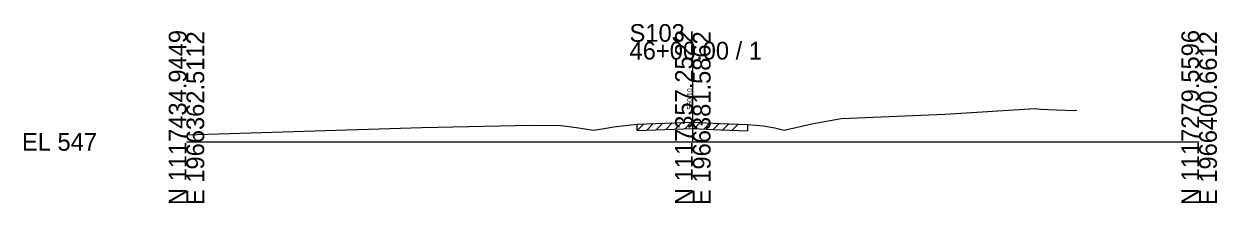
# Model space of a CAD drawing. Extents: x -26 to 163, y -10 to 45020.
# Drawn here: x -25.7 to 162.8, y 5990.3 to 6018.7 of the extents above; entities that cross this region are included whole.
import ezdxf

# ---------------------------------------------------------------- set-up
doc = ezdxf.new("R2010")
doc.units = 0
for name, color, linetype in [('RD_GPK_XS_Cell', 7, 'Continuous'), ('RD_XS_ExGround', 7, 'Continuous'), ('RD_XS_ExPaveRet', 7, 'Continuous'), ('RD_XS_TX_Elev_EX', 7, 'Continuous')]:
    doc.layers.add(name, color=color, linetype=linetype)

msp = doc.modelspace()

# ---------------------------------------------------------------- linework, layer by layer
at = {"layer": 'RD_GPK_XS_Cell'}
for p, q in [((80, 6000), (80, 6015.82)), ((0, 6000), (80, 6000)), ((80, 6000), (160, 6000))]:
    msp.add_line(p, q, dxfattribs=at)
at = {"layer": 'RD_XS_ExGround'}
for p, q in [((119.84, 6004.36), (134.09, 6005.27)), ((134.09, 6005.27), (134.94, 6005.19)), ((134.94, 6005.19), (140.08, 6004.96)), ((140.08, 6004.96), (140.68, 6005.02)), ((71.22, 6002.8), (75.57, 6002.96)), ((75.57, 6002.96), (79.95, 6003.11)), ((79.95, 6003.11), (84.38, 6002.92)), ((84.38, 6002.92), (88.64, 6002.72)), ((98.8, 6002.86), (103.44, 6003.71)), ((103.44, 6003.71), (119.84, 6004.36)), ((0, 6001.13), (37.19, 6002.29)), ((37.19, 6002.29), (54.36, 6002.62)), ((54.36, 6002.62), (59.12, 6002.61)), ((59.12, 6002.61), (61.61, 6002.25)), ((61.61, 6002.25), (64.27, 6001.85)), ((64.27, 6001.85), (66.05, 6002.13)), ((66.05, 6002.13), (67.49, 6002.36)), ((67.49, 6002.36), (69.3, 6002.59)), ((69.3, 6002.59), (71.22, 6002.8)), ((88.64, 6002.72), (89.98, 6002.64)), ((89.98, 6002.64), (91.11, 6002.55)), ((91.11, 6002.55), (92.95, 6002.2)), ((92.95, 6002.2), (94.45, 6001.86)), ((94.45, 6001.86), (98.8, 6002.86))]:
    msp.add_line(p, q, dxfattribs=at)
at = {"layer": 'RD_XS_ExPaveRet'}
for p, q in [((72.72, 6001.85), (73.76, 6002.89)), ((74.22, 6001.91), (75.26, 6002.95)), ((75.72, 6001.96), (76.76, 6003)), ((77.22, 6002.01), (78.26, 6003.05)), ((78.72, 6002.06), (79.76, 6003.1)), ((80.22, 6002.09), (81.18, 6003.05)), ((81.72, 6002.03), (82.68, 6002.99)), ((83.22, 6001.97), (84.18, 6002.92)), ((71.22, 6001.8), (72.26, 6002.84)), ((71.22, 6001.8), (71.22, 6002.8)), ((71.22, 6001.8), (75.57, 6001.96)), ((75.57, 6001.96), (79.95, 6002.11)), ((79.95, 6002.11), (84.38, 6001.92)), ((84.38, 6001.92), (88.64, 6001.72)), ((84.72, 6001.9), (85.68, 6002.86)), ((86.22, 6001.83), (87.18, 6002.79)), ((88.64, 6002.72), (88.64, 6001.72))]:
    msp.add_line(p, q, dxfattribs=at)

# ---------------------------------------------------------------- texts
at = {"layer": 'RD_GPK_XS_Cell'}
for s, p in [('S103', (70, 6015.82)), ('46+00.00 / 1', (70, 6013.02)), ('EL 547', (-26, 5998.6))]:
    msp.add_text(s, height=2.8, dxfattribs=at).set_placement(p)
for s, p in [('N 1117434.9449', (0, 5990)), ('E 1966362.5112', (2.8, 5990)), ('N 1117357.2522', (80, 5990)), ('E 1966381.5862', (82.8, 5990)), ('N 1117279.5596', (160, 5990)), ('E 1966400.6612', (162.8, 5990))]:
    msp.add_text(s, height=2.8, rotation=90, dxfattribs=at).set_placement(p)
at = {"layer": 'RD_XS_TX_Elev_EX'}
msp.add_text('550.10', height=0.8, rotation=90, dxfattribs=at).set_placement((79.9, 6005.1))

doc.saveas('drawing.dxf')
